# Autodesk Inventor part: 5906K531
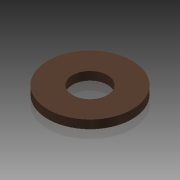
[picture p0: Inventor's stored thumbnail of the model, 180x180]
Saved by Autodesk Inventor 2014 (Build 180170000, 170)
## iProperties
Created: 2013-12
Part Number: 5906K531
Material: Bronze, Soft Tin
Document SubType Name: Modeling
Designer: Brad Factor
Density: 8.874 g/cm^3
Appearance: Bronze - Satin
Author: Brad Factor
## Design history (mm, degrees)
sketch "Sketch1"
  geometry: C1 r 3.302 at (0, 0); C2 r 7.938 at (0, 0); 1 further point
  constraints: 2 centre point, 2 coincident
  dimensions: "d0" = 6.604 diameter of C1; "d1" = 15.875 diameter of C2
extrude "Extrusion1" new body sketch "Sketch1" stored distance "d2" = 1.5875; taper "d3" = 0 deg
body "Solid1"
